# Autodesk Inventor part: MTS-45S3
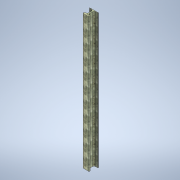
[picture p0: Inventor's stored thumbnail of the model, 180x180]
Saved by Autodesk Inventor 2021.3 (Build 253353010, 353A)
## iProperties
Created: 2021-11
Part Number: MTS-45S3
Material: Generic
Document SubType Name: Modeling
Designer: u1426
Density: 1 g/cm^3
Appearance: Precast Smooth
Author: u1426
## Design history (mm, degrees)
sketch "Sketch1"
  geometry: L1 (0, 0)-(-400.05, 0); L2 (-431.8, -31.75)-(-431.8, -143.319); L3 (-390.596, -202.776)-(-208.052, -271.231); L4 (-76.2, -461.493)-(-76.2, -849.936); L5 (-267.326, -1052.777)-(-573.764, -1071.017); L6 (-609.6, -1109.05)-(-609.6, -1143); L7 (0, 0)-(400.05, 0); L8 (431.8, -31.75)-(431.8, -143.319); L9 (390.596, -202.776)-(208.052, -271.231); L10 (76.2, -461.493)-(76.2, -849.936); L11 (267.326, -1052.777)-(573.764, -1071.017); L12 (609.6, -1109.05)-(609.6, -1143); L13 (609.6, -1143)-(-609.6, -1143); L14 (431.8, -31.75)-(400.05, 0); L15 (-400.05, 0)-(-431.8, -31.75); A1 r 38.1 centre (571.5, -1109.05) between (609.6, -1109.05) and (573.764, -1071.017); A2 r 38.1 centre (-571.5, -1109.05) between (-573.764, -1071.017) and (-609.6, -1109.05); A3 r 203.2 centre (-279.4, -849.936) between (-267.326, -1052.777) and (-76.2, -849.936); A4 r 203.2 centre (279.4, -849.936) between (76.2, -849.936) and (267.326, -1052.777); A5 r 203.2 centre (279.4, -461.493) between (208.052, -271.231) and (76.2, -461.493); A6 r 203.2 centre (-279.4, -461.493) between (-76.2, -461.493) and (-208.052, -271.231); A7 r 63.5 centre (368.3, -143.319) between (390.596, -202.776) and (431.8, -143.319); A8 r 63.5 centre (-368.3, -143.319) between (-431.8, -143.319) and (-390.596, -202.776); 10 further points
  constraints: 30 end point, 20 point on line, 16 point on circle, 16 tangent, 8 centre point, 5 equal radius, 3 parallel, 3 perpendicular, 2 horizontal, 1 vertical
  dimensions: "d0" = 431.8 distance of L1.start point (-431.8, 0); "d1" = 187.325 distance of point (-431.8, 0) point (-431.8, -187.325); "d2" = 355.6 horizontal distance of point (-431.8, -187.325) point (-76.2, -320.675); "d3" = 133.35 vertical distance of point (-431.8, -187.325) point (-76.2, -320.675); "d4" = 31.75 vertical distance of point (-76.2, -1041.4) point (-609.6, -1073.15); "d5" = 69.85 distance of point (-609.6, -1073.15) L6.end; "d7" = 533.4 horizontal distance of point (-76.2, -1041.4) point (-609.6, -1073.15); "d8" = 431.8 distance of L1.start point (431.8, 0); "d9" = 187.325 distance of point (431.8, 0) point (431.8, -187.325); "d10" = 355.6 horizontal distance of point (431.8, -187.325) point (76.2, -320.675); "d11" = 133.35 vertical distance of point (431.8, -187.325) point (76.2, -320.675); "d12" = 533.4 horizontal distance of point (76.2, -1041.4) point (609.6, -1073.15); "d13" = 31.75 vertical distance of point (76.2, -1041.4) point (609.6, -1073.15); "d14" = 1143 distance between parallel lines of L1 L13; "d15" = 69.85 distance of point (609.6, -1073.15) L12.end; "d16" = 1219.2 distance between parallel lines of L6 L12 (derived); "d17" = 863.6 distance between parallel lines of L2 L8 (derived); "d18" = 152.4 distance between parallel lines of L4 L10 (derived); "d19" = 38.1 radius of A1; "d20" = 203.2 radius of A3; "d21" = 63.5 radius of A7; "d22" = 31.75 distance of L8.start point (431.8, 0); "d23" = 31.75 distance of L7.end point (431.8, 0) (= d22); "d24" = 31.75 distance of L1.end point (-431.8, 0) (= d22); "d25" = 31.75 distance of L2.start point (-431.8, 0) (= d24)
extrude "Extrusion1" new body sketch "Sketch1" distance "d26" = 18745.2; taper "d27" = 0 deg
body "Solid1"
